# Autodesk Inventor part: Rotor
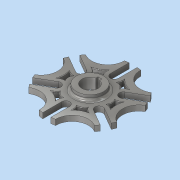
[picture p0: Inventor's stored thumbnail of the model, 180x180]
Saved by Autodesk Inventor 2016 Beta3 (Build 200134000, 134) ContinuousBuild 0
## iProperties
Created: 2015-11
Part Number: Rotor
Material: Aluminum 6061-AHC
Document SubType Name: Modeling
Designer: SanPer86
Density: 2.7 g/cm^3
Appearance: Aluminum - Dark
Mass: 0.0400359 g
Surface Area: 0.948584 cm^2
Volume: 0.0148281 cm^3
Author: SanPer86
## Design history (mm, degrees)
sketch "Sketch1"
  geometry: L1 (2.136, 0.8)-(3.636, 1.666); L2 (3, 0)-(0, 0); L3 (0, 0)-(1.624, 0.937); A1 r 0.375 centre (1.949, 1.125) between (1.624, 0.937) and (2.136, 0.8); A2 r 4 centre (0, 0) between (3.778, 1.315) and (3.636, 1.666); A3 r 1.5 centre (4.5, 0) between (3.778, 1.315) and (3, 0)
  constraints: 6 end point, 6 point on circle, 3 centre point, 2 point on line, 1 horizontal, 1 parallel, 1 tangent
  dimensions: "d26" = 1.5 radius of A3; "d27" = 4.5 distance of A3.centre A2.centre; "d28" = 30 deg angle of L2 L3; "d29" = 0.375 radius of A1; "d30" = 2.25 distance of L2.end A1.centre; "d31" = 4 radius of A2
extrude "Extrusion1" new body sketch "Sketch1" distance "d38" = 0.5; taper "d39" = 0 deg
mirror "Mirror1"
pattern_circular "Circular Pattern1" dims angle "d41" = 360 deg
sketch "Sketch2"
  geometry: L1 (-3.449, -1.991)-(0, 0); L2 (0, -3.982)-(0, 0); L3 (3.449, -1.991)-(0, 0); L4 (3.449, 1.991)-(0, 0); L5 (0, 3.982)-(0, 0); L6 (-3.449, 1.991)-(0, 0); C1 r 1.25 at (0, 0); 1 further point
  constraints: 12 end point, 2 coincident, 1 centre point, 19 other
  dimensions: "d43" = 2.5 diameter of C1; "d51" = 360 deg dimension on point (0, 0) L1.start (derived)
extrude "Extrusion2" join sketch "Sketch2" distance "d56" = 0.5; taper "d57" = 0 deg
sketch "Sketch3"
  geometry: C1 r 0.75 at (0, 0); 1 further point
  constraints: 1 centre point, 1 coincident
  dimensions: "d58" = 1.5 diameter of C1
extrude "Extrusion3" cut sketch "Sketch3" distance "d59" = 1; taper "d60" = 0 deg
fillet "Fillet1" dims "d61" = 0.25
sketch "Sketch4"
  geometry: L1 (0.18, 0.728)-(0.18, 0.928); L2 (0.18, 0.928)-(-0.18, 0.928); L3 (-0.18, 0.928)-(-0.18, 0.728); A1 r 0.75 centre (0, 0) between (0.18, 0.728) and (-0.18, 0.728) reference; A2 r 0.75 centre (0, 0) between (0.18, 0.728) and (-0.18, 0.728); 1 further point
  constraints: 6 end point, 4 point on circle, 2 concentric, 2 perpendicular, 1 centre point
  dimensions: "d64" = 0.36 distance of L1.end L2.end; "d65" = 0.2 distance of L1.start L1.end; "d66" = 0.2 distance of L2.end L3.end
extrude "Extrusion4" cut sketch "Sketch4" distance "d67" = 1; taper "d68" = 0 deg
sketch "Sketch5"
  geometry: L1 (0.775, -2.25)-(0.775, -2.377); L2 (1.561, -1.796)-(1.671, -1.86); A1 r 0.775 centre (1.949, -1.125) between (1.288, -1.53) and (1.561, -1.796); A2 r 0.775 centre (0, -2.25) between (0.775, -2.25) and (0.681, -1.88); A3 r 1.965 centre (2.171, -3.76) between (1.671, -1.86) and (0.775, -2.377); A4 r 0.74 centre (0.659, -1.141) between (0.681, -1.88) and (1.288, -1.53); 2 further points
  constraints: 8 point on circle, 4 centre point, 4 end point
extrude "Extrusion5" cut sketch "Sketch5" distance "d73" = 0.6; taper "d74" = 0 deg
fillet "Fillet2" dims "d75" = 0.05
pattern_circular "Circular Pattern2" dims angle "d77" = 360 deg
body "Solid1"
other parameters: "d0" = 19.05 (derived), "d2" = 114.3 (derived), "d4" = 38.1 (derived), "d6" = 38.1 (derived), "d8" = 60 deg (derived), "d10" = 114.3 (derived), "d13" = 114.3 (derived), "d15" = 38.1 (derived), "d17" = 60 deg (derived), "d19" = 114.3 (derived), "d21" = 38.1 (derived), "d23" = 19.05 (derived), "d71" = 0.4
